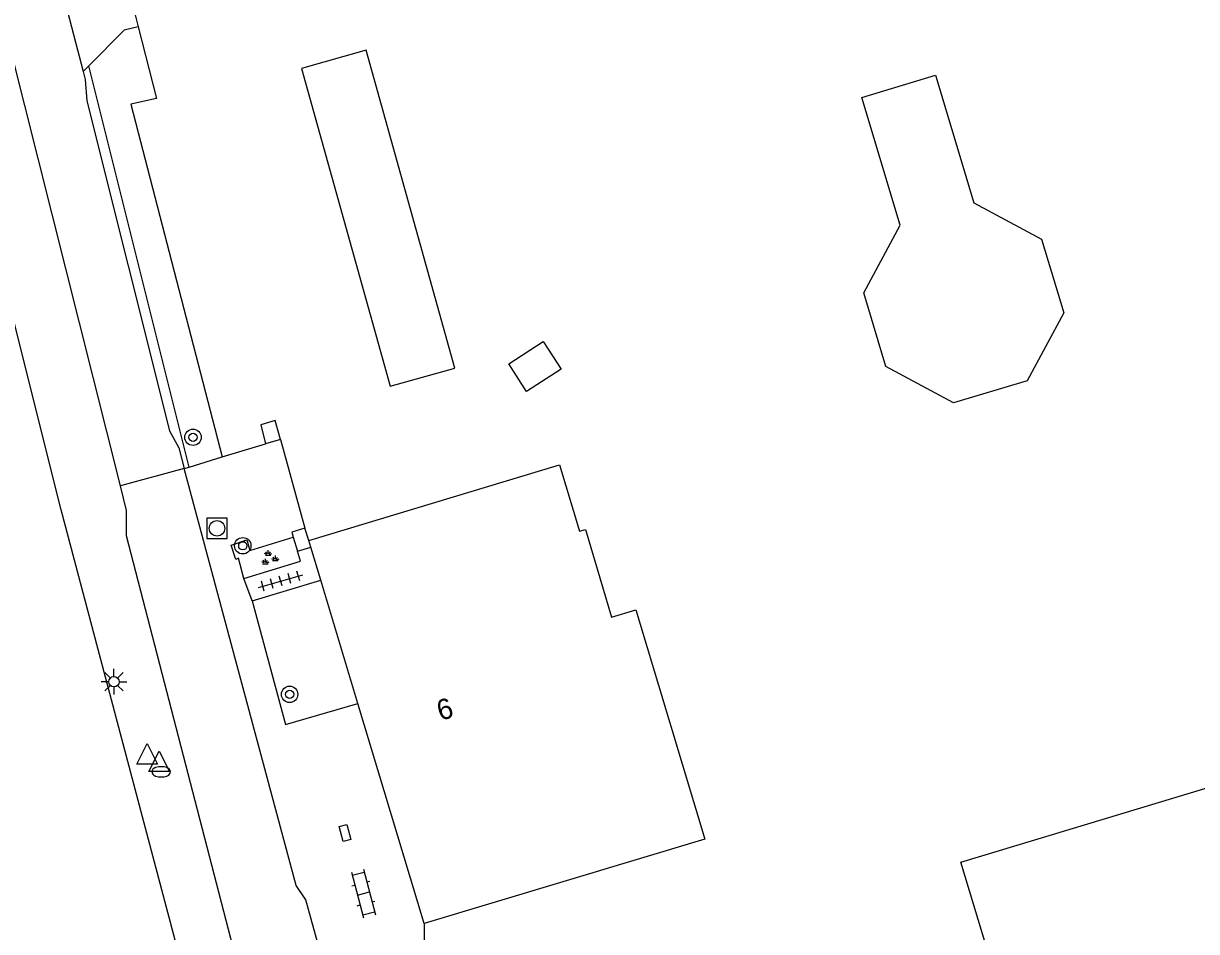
# Model space of a CAD drawing. Extents: x 124000 to 129000, y 395500 to 397503.
# Drawn here: x 126731.1 to 126788.3, y 397039.3 to 397083.6 of the extents above; entities that cross this region are included whole.
import ezdxf

# ---------------------------------------------------------------- set-up
doc = ezdxf.new("R2010")
doc.units = 0
for name, color, linetype in [('gg-afsc-muur', 7, 'Continuous'), ('gg-anno-huisnummerreeks BGT', 7, 'Continuous'), ('gg-bbg-bijgebouw', 7, 'Continuous'), ('gg-bbg-gedigitaliseerde bijgebouw', 7, 'Continuous'), ('gg-bbg-hoofdgebouw', 7, 'Continuous'), ('gg-knt-verharding', 7, 'Continuous'), ('gt-grn-groengrens', 7, 'Continuous'), ('gt-grn-weggrens', 7, 'Continuous'), ('gt-symb-boom', 7, 'Continuous'), ('gt-symb-brandkraan', 7, 'Continuous'), ('gt-symb-groenvak', 7, 'Continuous'), ('gt-symb-klinker verharding', 7, 'Continuous'), ('gt-symb-kolk center center', 7, 'Continuous'), ('gt-symb-lichtmast', 7, 'Continuous'), ('gt-symb-rioolschacht', 7, 'Continuous'), ('gt-symb-tegel verharding', 7, 'Continuous'), ('gt-symb-waterafsluiter', 7, 'Continuous')]:
    doc.layers.add(name, color=color, linetype=linetype)

# ---------------------------------------------------------------- blocks, each defined once
blk = doc.blocks.new('gt0-BOOM')
at = {"layer": 'gt-symb-boom'}
for radius in [0.4, 0.2]:
    blk.add_circle((0, 0), radius, dxfattribs=at)
blk = doc.blocks.new('gt0-RS')
at = {"layer": 'gt-symb-rioolschacht'}
blk.add_lwpolyline([(-0.5, -0.5), (0.5, -0.5), (0.5, 0.5), (-0.5, 0.5)], close=True, dxfattribs=at)
blk.add_circle((0, 0), 0.375, dxfattribs=at)
blk = doc.blocks.new('gt0-LMAST')
at = {"layer": 'gt-symb-lichtmast'}
for p, q in [((-0.005, 0.246), (-0.005, 0.621)), ((-0.182, 0.173), (-0.447, 0.438)), ((0.172, 0.173), (0.437, 0.438)), ((-0.255, -0.004), (-0.63, -0.004)), ((-0.182, -0.181), (-0.447, -0.446)), ((-0.005, -0.254), (-0.005, -0.629)), ((0.437, -0.446), (0.172, -0.181)), ((0.245, -0.004), (0.62, -0.004))]:
    blk.add_line(p, q, dxfattribs=at)
blk.add_circle((-0.005, -0.004), 0.25, dxfattribs=at)
blk = doc.blocks.new('gt0-WAFSL')
at = {"layer": 'gt-symb-waterafsluiter'}
for p, q in [((-0.5, -0.333), (0, 0.667)), ((0, 0.667), (0.5, -0.333)), ((0.5, -0.333), (-0.5, -0.333))]:
    blk.add_line(p, q, dxfattribs=at)
blk = doc.blocks.new('gt0-BR')
at = {"layer": 'gt-symb-brandkraan'}
for centre, radius, start, end in [((-0.244, 0), 0.206, 107.5669, 252.4331), ((0.599, -2.664), 3, 106.892, 107.5669), ((0, -0.691), 0.938, 73.108, 106.892), ((-0.599, -2.664), 3, 72.4331, 73.108), ((0.244, 0), 0.206, 287.567, 72.4331), ((0.599, 2.664), 3, 252.4331, 253.108), ((0, 0.691), 0.938, 253.108, 286.8921), ((-0.599, 2.664), 3, 286.8921, 287.567)]:
    blk.add_arc(centre, radius, start, end, dxfattribs=at)
blk = doc.blocks.new('gt0-GRVAK')
at = {"layer": 'gt-symb-groenvak'}
for p, q in [((-0.11, 0.189), (-0.228, 0.24)), ((-0.182, 0.153), (0.088, 0.153)), ((-0.091, 0.211), (-0.156, 0.322)), ((-0.047, 0.214), (-0.047, 0.393)), ((-0.004, 0.211), (0.061, 0.322)), ((0.015, 0.189), (0.133, 0.24)), ((0.262, -0.052), (0.197, 0.059)), ((0.305, -0.049), (0.305, 0.13)), ((0.349, -0.052), (0.414, 0.059)), ((-0.245, -0.228), (-0.363, -0.177)), ((-0.318, -0.264), (-0.047, -0.264)), ((-0.226, -0.206), (-0.291, -0.095)), ((-0.183, -0.203), (-0.183, -0.024)), ((-0.139, -0.206), (-0.074, -0.095)), ((-0.12, -0.228), (-0.002, -0.177)), ((0.243, -0.074), (0.125, -0.023)), ((0.17, -0.11), (0.441, -0.11)), ((0.368, -0.074), (0.486, -0.023))]:
    blk.add_line(p, q, dxfattribs=at)
blk = doc.blocks.new('gt0-TEG1')
at = {"layer": 'gt-symb-tegel verharding'}
for p, q in [((-1.125, 0), (1.125, 0)), ((-0.9, -0.25), (-0.9, 0.25)), ((-0.45, -0.25), (-0.45, 0.25)), ((0, -0.25), (0, 0.25)), ((0.45, -0.25), (0.45, 0.25)), ((0.9, -0.25), (0.9, 0.25))]:
    blk.add_line(p, q, dxfattribs=at)
blk = doc.blocks.new('gt0-KOLKCC')
at = {"layer": 'gt-symb-kolk center center'}
blk.add_lwpolyline([(-0.375, 0.2), (0.375, 0.2), (0.375, -0.2), (-0.375, -0.2)], close=True, dxfattribs=at)
blk = doc.blocks.new('gt0-KL1')
at = {"layer": 'gt-symb-klinker verharding'}
for p, q in [((-1.15, 0.3), (1.15, 0.3)), ((-1, -0.3), (-1, 0.3)), ((-0.5, 0.3), (-0.5, 0.45)), ((0, -0.3), (0, 0.3)), ((0.5, 0.3), (0.5, 0.45)), ((1, -0.3), (1, 0.3)), ((-1.15, -0.3), (1.15, -0.3)), ((-0.5, -0.45), (-0.5, -0.3)), ((0.5, -0.45), (0.5, -0.3))]:
    blk.add_line(p, q, dxfattribs=at)

msp = doc.modelspace()

# ---------------------------------------------------------------- linework, layer by layer
at = {"layer": 'gg-afsc-muur'}
for p, q in [((126743.59, 397063.295), (126742.861, 397063.087)), ((126744.213, 397058.525), (126744.42, 397057.85)), ((126744.971, 397058.367), (126744.779, 397058.974)), ((126744.971, 397058.367), (126744.779, 397058.974)), ((126744.42, 397057.85), (126745.067, 397058.048))]:
    msp.add_line(p, q, dxfattribs=at)
for points in [[(126743.59, 397063.295), (126743.335, 397064.217), (126742.626, 397064.011), (126742.861, 397063.087)], [(126744.779, 397058.974), (126744.137, 397058.774), (126744.213, 397058.525)]]:
    msp.add_lwpolyline(points, dxfattribs=at)
at = {"layer": 'gg-bbg-bijgebouw'}
for points in [[(126748.933, 397065.89), (126752.097, 397066.773), (126747.771, 397082.265), (126744.608, 397081.382), (126748.933, 397065.89)], [(126781.724, 397026.294), (126776.767, 397042.684), (126795.885, 397048.449), (126807.473, 397010.175)]]:
    msp.add_lwpolyline(points, dxfattribs=at)
at = {"layer": 'gg-bbg-gedigitaliseerde bijgebouw'}
for p, q in [((126771.934, 397079.969), (126775.526, 397081.049)), ((126773.806, 397073.745), (126771.934, 397079.969)), ((126755.588, 397065.636), (126754.723, 397066.982))]:
    msp.add_line(p, q, dxfattribs=at)
for points in [[(126775.526, 397081.049), (126777.398, 397074.826), (126780.701, 397073.051), (126781.781, 397069.46), (126780.005, 397066.157), (126776.414, 397065.077), (126773.111, 397066.852), (126772.031, 397070.443), (126773.806, 397073.745)], [(126754.723, 397066.982), (126756.405, 397068.064), (126757.27, 397066.718), (126755.588, 397065.636)]]:
    msp.add_lwpolyline(points, dxfattribs=at)
at = {"layer": 'gg-bbg-hoofdgebouw'}
for p, q in [((126745.067, 397058.048), (126744.971, 397058.367)), ((126745.552, 397056.437), (126745.067, 397058.048)), ((126747.362, 397050.42), (126745.552, 397056.437)), ((126750.589, 397039.691), (126747.362, 397050.42)), ((126764.285, 397043.805), (126750.589, 397039.691))]:
    msp.add_line(p, q, dxfattribs=at)
msp.add_lwpolyline([(126744.971, 397058.367), (126757.188, 397062.063), (126758.17, 397058.818), (126758.467, 397058.908), (126759.739, 397054.632), (126760.917, 397054.987), (126764.285, 397043.805)], dxfattribs=at)
at = {"layer": 'gg-knt-verharding'}
for p, q in [((126732.194, 397088.064), (126733.969, 397081.228)), ((126734.25, 397081.512), (126733.969, 397081.228)), ((126740.741, 397062.439), (126742.861, 397063.087)), ((126738.899, 397061.876), (126739.13, 397061.947)), ((126739.13, 397061.947), (126740.741, 397062.439)), ((126742.208, 397055.431), (126741.808, 397056.512)), ((126742.208, 397055.431), (126745.552, 397056.437))]:
    msp.add_line(p, q, dxfattribs=at)
for points in [[(126735.784, 397061.041), (126730.464, 397082.225), (126725.435, 397102.577), (126718.864, 397129.809), (126713.537, 397149.433), (126710.52, 397159.394)], [(126736.659, 397083.413), (126735.964, 397083.243), (126734.25, 397081.512)], [(126733.969, 397081.228), (126734.066, 397080.848), (126734.144, 397079.797), (126738.185, 397063.711), (126738.628, 397062.881), (126738.899, 397061.876)], [(126748.996, 397025.718), (126744.834, 397040.855), (126744.353, 397041.543), (126738.899, 397061.876)], [(126752.172, 397000), (126748.914, 397012.218), (126747.176, 397016.8), (126742.205, 397034.951), (126736.075, 397058.596), (126736.09, 397059.824), (126735.784, 397061.041)], [(126741.808, 397056.512), (126741.54, 397057.499), (126741.412, 397057.44), (126741.182, 397058.145), (126741.942, 397058.394), (126742.102, 397057.875), (126744.213, 397058.525)], [(126741.808, 397056.512), (126744.571, 397057.359), (126744.42, 397057.85)], [(126742.208, 397055.431), (126743.838, 397049.396), (126747.362, 397050.42)]]:
    msp.add_lwpolyline(points, dxfattribs=at)
at = {"layer": 'gt-grn-groengrens'}
msp.add_line((126739.13, 397061.947), (126734.25, 397081.512), dxfattribs=at)
for points in [[(126762.86, 396945.066), (126748.816, 397000), (126744.577, 397015.769), (126732.9, 397059.863), (126716.157, 397126.672), (126711.926, 397142.797), (126705.272, 397166.023), (126694.756, 397192.794), (126682.182, 397219.558), (126674.665, 397234.422)], [(126736.659, 397083.413), (126737.541, 397079.914), (126736.293, 397079.64), (126740.741, 397062.439)]]:
    msp.add_lwpolyline(points, dxfattribs=at)
at = {"layer": 'gt-grn-weggrens'}
for p, q in [((126735.549, 397087.819), (126736.659, 397083.413)), ((126743.59, 397063.295), (126744.779, 397058.974)), ((126738.899, 397061.876), (126735.784, 397061.041)), ((126750.589, 397039.691), (126750.647, 397034.778))]:
    msp.add_line(p, q, dxfattribs=at)

# ---------------------------------------------------------------- block references
at = {"layer": 'gt-symb-boom'}
for p in [(126739.325, 397063.4), (126741.752, 397058.111), (126744.036, 397050.868)]:
    msp.add_blockref('gt0-BOOM', p, dxfattribs=at)
at = {"layer": 'gt-symb-brandkraan'}
msp.add_blockref('gt0-BR', (126737.776, 397047.092), dxfattribs=at)
at = {"layer": 'gt-symb-groenvak'}
msp.add_blockref('gt0-GRVAK', (126743.038, 397057.5), dxfattribs=at)
at = {"layer": 'gt-symb-klinker verharding', "rotation": -75.17189147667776}
msp.add_blockref('gt0-KL1', (126747.635, 397041.161), dxfattribs=at)
at = {"layer": 'gt-symb-kolk center center', "rotation": -74.86552497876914}
msp.add_blockref('gt0-KOLKCC', (126746.737, 397044.109), dxfattribs=at)
at = {"layer": 'gt-symb-lichtmast'}
msp.add_blockref('gt0-LMAST', (126735.476, 397051.488), dxfattribs=at)
at = {"layer": 'gt-symb-rioolschacht'}
msp.add_blockref('gt0-RS', (126740.496, 397058.961), dxfattribs=at)
at = {"layer": 'gt-symb-tegel verharding', "rotation": 15.969016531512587}
msp.add_blockref('gt0-TEG1', (126743.599, 397056.391), dxfattribs=at)
at = {"layer": 'gt-symb-waterafsluiter'}
for p in [(126737.094, 397047.797), (126737.676, 397047.439)]:
    msp.add_blockref('gt0-WAFSL', p, dxfattribs=at)

# ---------------------------------------------------------------- texts
at = {"layer": 'gg-anno-huisnummerreeks BGT'}
msp.add_text('6', height=1, rotation=16.7, dxfattribs=at).set_placement((126751.389, 397049.569))

doc.saveas('drawing.dxf')
